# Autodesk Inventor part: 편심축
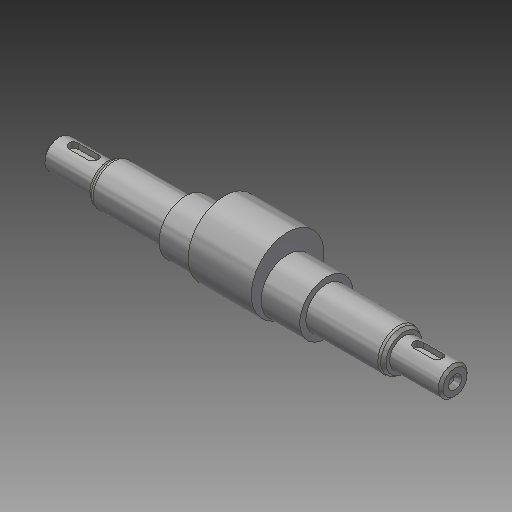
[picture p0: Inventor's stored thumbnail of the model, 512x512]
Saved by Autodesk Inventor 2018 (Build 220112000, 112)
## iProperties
Created: 2019-01
Part Number: 편심축
Material: 강철, 연강
Document SubType Name: Modeling
Designer: mduedu
Density: 7.86 g/cm^3
Appearance: 강철
Mass: 387.265 g
Surface Area: 112.621 cm^2
Volume: 49.2703 cm^3
Author: mduedu
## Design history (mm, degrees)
sketch "스케치1"
  geometry: L1 (0, 0)-(21, 0); L2 (21, 0)-(21, 6); L3 (21, 6)-(0, 6); L4 (0, 6)-(0, 0); L5 (21, 0)-(53, 0); L6 (53, 0)-(53, 8.5); L7 (53, 8.5)-(21, 8.5); L8 (21, 8.5)-(21, 0); L9 (53, 0)-(111, 0); L10 (111, 0)-(111, 11); L11 (111, 11)-(53, 11); L12 (53, 11)-(53, 0); L13 (82, 11)-(82, 0); L14 (111, 0)-(143, 0); L15 (143, 0)-(143, 8.5); L16 (143, 8.5)-(111, 8.5); L17 (111, 8.5)-(111, 0); L18 (143, 0)-(164, 0); L19 (164, 0)-(164, 6); L20 (164, 6)-(143, 6); L21 (143, 6)-(143, 0)
  constraints: 42 end point, 10 parallel, 5 horizontal, 5 perpendicular, 4 collinear, 2 midpoint
  dimensions: "d3" = 58 distance of L10.end L11.end; "d5" = 12 diameter of L3 L1; "d6" = 17 diameter of L7 L5; "d8" = 22 diameter of L11 L9; "d51" = 164 distance between parallel lines of L4 L19; "d52" = 122 distance between parallel lines of L2 L15; "d53" = 32 distance of L15.end L16.end (derived); "d54" = 32 distance of L6.end L7.end (derived)
revolve "회전1" sketch "스케치1" stored, may be unused: angle "d9" = 90 deg
node "작업 평면3"
sketch "스케치2"
  geometry: C1 r 15 at (0, 4); C2 r 11 at (0, 0); 1 further point
  constraints: 2 centre point, 1 tangent, 1 vertical alignment
  dimensions: "d11" = 4 distance of point (0, 0) C1.centre
extrude "돌출1" join sketch "스케치2" distance "d12" = 26; taper "d13" = 0 deg
node "작업 평면2"
sketch "스케치3" dims "d16" = 12
  geometry: L1 (-4.5, 2)-(3.5, 2); L2 (3.5, 2)-(3.5, -2); L3 (3.5, -2)-(-4.5, -2); L4 (-4.5, -2)-(-4.5, 2); L5 (-10.5, 8.5)-(-10.5, -8.5) reference; 3 further points
  constraints: 8 end point, 2 midpoint, 2 parallel, 2 vertical alignment, 1 horizontal, 1 horizontal alignment, 1 perpendicular, 4 other
  dimensions: "d14" = 4 distance between parallel lines of L3 L1; "d17" = 4 dimension on L5
extrude "돌출2" cut sketch "스케치3" distance "d18" = 2.5; taper "d19" = 0 deg
node "작업 평면4"
chamfer "모따기1" distance "d20" = 1.82; stored, may be unused: second distance "d21" = 2, angle "d22" = 30 deg
chamfer "모따기3" distance "d56" = 1.82; stored, may be unused: second distance "d57" = 2, angle "d58" = 30 deg
fillet "모깎기1" dims "d23" = 2
hole "구멍2" diameter "d39" = 3.242; stored, may be unused: countersink angle "d43" = 60 deg, drill point angle "d45" = 118 deg; dims "d37" = 10, "d38" = 10, "d40" = 8, "d41" = 5.51, "d42" = 2, "d44" = 10
sketch "스케치5"
  geometry: L1 (0, 0)-(2, 0); L2 (2, 0)-(2, 1.621); L3 (0, 2.776)-(0, 0); L4 (0, 2.776)-(2, 1.621); L5 (10, 1.621)-(0, 1.621) reference
  constraints: 8 end point, 1 horizontal, 1 parallel, 1 perpendicular, 1 point on line
  dimensions: "d46" = 2 distance between parallel lines of L2 L3; "d48" = 30 deg angle of L4 L1
revolve "회전2" sketch "스케치5" stored, may be unused: angle "d50" = 90 deg
chamfer "모따기2" distance "d25" = 1; stored, may be unused: second distance "d26" = 2, angle "d27" = 30 deg
node "솔리드1"
mirror "대칭1"
mirror "대칭2"
mirror "대칭3"
other parameters: "d55" = -16
